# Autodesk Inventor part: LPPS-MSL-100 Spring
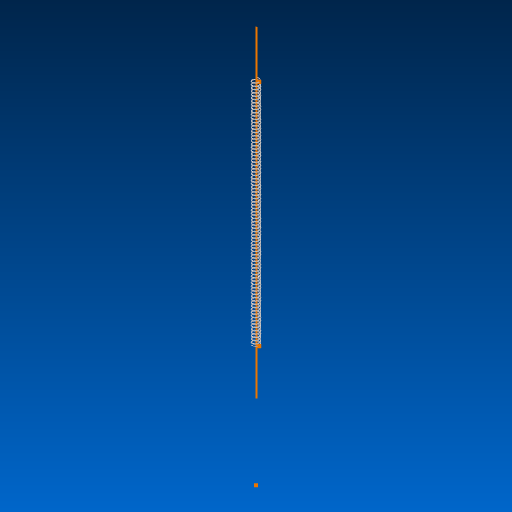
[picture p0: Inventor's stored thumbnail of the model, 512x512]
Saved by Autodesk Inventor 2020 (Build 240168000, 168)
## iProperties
Created: 2019-07
Part Number: LPPS-MSL-100 Spring
Material: Stainless Steel
Document SubType Name: Modeling
Designer: J. Nielson
Density: 8 g/cm^3
Appearance: Semi-Polished
Author: J. Nielson
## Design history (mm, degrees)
sketch "Sketch1"
  geometry: L1 (4, 74.746)-(-4, 74.746) reference; L2 (-2.5, 215.404)-(2.5, 215.404) reference; L3 (0, 215.404)-(0, 74.746); C1 r 0.152 at (1.905, 74.898); 1 further point
  constraints: 2 end point, 2 midpoint, 1 centre point, 1 tangent
  dimensions: "d0" = 0.3048 diameter of C1; "d1" = 1.905 distance from line of L3 C1.centre; "d2" = 140.658 distance between parallel lines of L2 L1 (derived)
coil "Coil1" sketch "Sketch1" pitch "d3" = 25.4; turns "d5" = 80; dims "d4" = 140.3532 (= d2 - d0), "d6" = 0, angle "d7" = 180 deg, angle "d8" = 180 deg, "d9" = 5 deg, "d10" = 180 deg
sketch "Sketch2"
  geometry: L1 (1.905, -168.637)-(1.905, 28.284) reference; 5 further points
  constraints: 2 horizontal alignment
  node "Projected Loop1"
revolve "Revolution1" stored, may be unused: angle "d11" = 110 deg
revolve "Revolution2" stored, may be unused: angle "d12" = 110 deg
body "Solid1"
node "Reference1"
node "Reference2"
